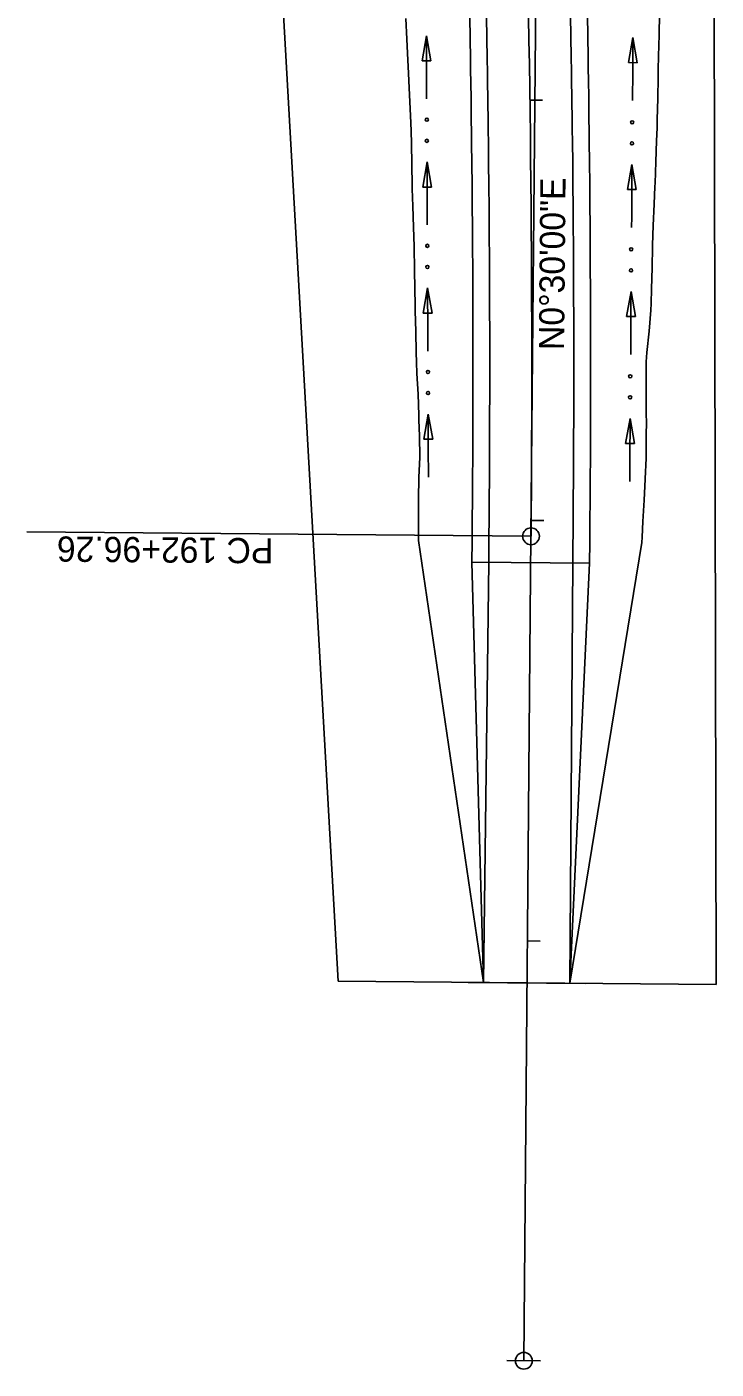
# Model space of a CAD drawing. Extents: x 1 to 1477871, y 1 to 1872901.
# Drawn here: x 1438513.3 to 1438677.3, y 1869035 to 1869354.3 of the extents above; entities that cross this region are included whole.
import ezdxf

# ---------------------------------------------------------------- set-up
doc = ezdxf.new("R2010")
doc.units = 0
for name, color, linetype in [('R_Horz Alg', 7, 'Continuous'), ('R_Horz Alg Annot', 7, 'Continuous'), ('R_No Plot', 7, 'Continuous'), ('R_Proposed Const Limits_Cut', 7, 'Continuous'), ('R_Proposed Road_Lane', 7, 'Continuous'), ('R_Proposed Road_Shoulder', 7, 'Continuous'), ('R_ROW', 7, 'Continuous'), ('R_Water', 7, 'Continuous')]:
    doc.layers.add(name, color=color, linetype=linetype)

msp = doc.modelspace()

# ---------------------------------------------------------------- linework, layer by layer
at = {"layer": 'R_Horz Alg'}
msp.add_line((1438631.55, 1869037.01), (1438633.26, 1869233.13), dxfattribs=at)
msp.add_arc((1434049.78, 1869273.13), 4583.66, 359.5, 3.99213, dxfattribs=at)
at = {"layer": 'R_Horz Alg Annot'}
msp.add_line((1438633.26, 1869233.13), (1438634.83, 1869412.9), dxfattribs=at)
for points in [[(1438635.99, 1869336.91), (1438632.99, 1869336.87)], [(1438633.26, 1869233.13), (1438513.27, 1869234.18)], [(1438636.29, 1869236.85), (1438633.29, 1869236.87)], [(1438635.42, 1869136.85), (1438632.42, 1869136.87)], [(1438627.55, 1869037.05), (1438635.55, 1869036.98)], [(1438627.55, 1869037.05), (1438635.55, 1869036.98)]]:
    msp.add_lwpolyline(points, dxfattribs=at)
for centre in [(1438633.26, 1869233.13), (1438631.55, 1869037.01)]:
    msp.add_circle(centre, 2, dxfattribs=at)
at = {"layer": 'R_No Plot'}
for p, q in [((1438619.21, 1869226.99), (1438647.21, 1869226.75)), ((1438618.34, 1869127), (1438646.33, 1869126.75))]:
    msp.add_line(p, q, dxfattribs=at)
at = {"layer": 'R_Proposed Const Limits_Cut'}
for points in [[(1438621.97, 1869126.96), (1438606.5, 1869232.1), (1438606.49, 1869233.36), (1438606.45, 1869237.08), (1438606.5, 1869242.05), (1438606.58, 1869247.02), (1438606.58, 1869247.1), (1438606.83, 1869251.99), (1438606.71, 1869256.96), (1438606.6, 1869260.85), (1438606.57, 1869261.94), (1438606.37, 1869266.91), (1438606.07, 1869271.88), (1438605.99, 1869274.59), (1438605.94, 1869276.85), (1438605.82, 1869281.82), (1438605.71, 1869286.79), (1438605.68, 1869288.32), (1438605.61, 1869291.76), (1438605.53, 1869296.73), (1438605.46, 1869301.69), (1438605.45, 1869302.06), (1438605.3, 1869306.66), (1438605.12, 1869311.63), (1438604.99, 1869315.8), (1438604.98, 1869316.6), (1438604.9, 1869321.57), (1438604.79, 1869326.54), (1438604.71, 1869329.53), (1438604.66, 1869331.5), (1438604.46, 1869336.47), (1438604.2, 1869341.44), (1438604.1, 1869343.26), (1438603.94, 1869346.4), (1438603.7, 1869351.37), (1438603.47, 1869356.33)], [(1438642.52, 1869126.79), (1438659.62, 1869231.64), (1438659.69, 1869232.9), (1438659.89, 1869236.66), (1438660.19, 1869241.69), (1438660.44, 1869246.71), (1438660.44, 1869246.8), (1438660.64, 1869251.74), (1438660.7, 1869256.77), (1438660.72, 1869260.7), (1438660.71, 1869261.8), (1438660.67, 1869266.83), (1438660.66, 1869271.86), (1438660.66, 1869274.6), (1438660.86, 1869276.89), (1438661.35, 1869281.92), (1438661.79, 1869286.95), (1438661.88, 1869288.51), (1438661.98, 1869291.99), (1438662.1, 1869297.02), (1438662.17, 1869302.05), (1438662.17, 1869302.42), (1438662.32, 1869307.08), (1438662.57, 1869312.12), (1438662.77, 1869316.34), (1438662.78, 1869317.15), (1438662.95, 1869322.19), (1438663.14, 1869327.22), (1438663.26, 1869330.26), (1438663.33, 1869332.26), (1438663.43, 1869337.29), (1438663.5, 1869342.32), (1438663.53, 1869344.17), (1438663.62, 1869347.36), (1438663.74, 1869352.4), (1438663.85, 1869357.43)]]:
    msp.add_lwpolyline(points, dxfattribs=at)
at = {"layer": 'R_Proposed Road_Lane'}
for p, q in [((1438623.21, 1869226.96), (1438621.97, 1869126.96)), ((1438643.21, 1869226.78), (1438642.52, 1869126.79))]:
    msp.add_line(p, q, dxfattribs=at)
for points in [[(1438623.21, 1869226.96), (1438623.25, 1869231.96), (1438623.26, 1869233.22), (1438623.29, 1869236.95), (1438623.33, 1869241.94), (1438623.36, 1869246.93), (1438623.36, 1869247.01), (1438623.39, 1869251.92), (1438623.41, 1869256.91), (1438623.42, 1869260.8), (1438623.42, 1869261.89), (1438623.43, 1869266.88), (1438623.44, 1869271.87), (1438623.44, 1869274.59), (1438623.44, 1869276.86), (1438623.43, 1869281.85), (1438623.42, 1869286.84), (1438623.41, 1869288.38), (1438623.4, 1869291.83), (1438623.38, 1869296.82), (1438623.35, 1869301.81), (1438623.34, 1869302.18), (1438623.31, 1869306.79), (1438623.27, 1869311.78), (1438623.24, 1869315.97), (1438623.23, 1869316.77), (1438623.18, 1869321.76), (1438623.12, 1869326.75), (1438623.09, 1869329.76), (1438623.06, 1869331.74), (1438623, 1869336.73), (1438622.92, 1869341.72), (1438622.9, 1869343.55), (1438622.84, 1869346.71), (1438622.76, 1869351.69), (1438622.67, 1869356.68)], [(1438643.21, 1869226.78), (1438643.25, 1869231.78), (1438643.26, 1869233.04), (1438643.29, 1869236.79), (1438643.33, 1869241.8), (1438643.36, 1869246.81), (1438643.36, 1869246.89), (1438643.39, 1869251.82), (1438643.41, 1869256.83), (1438643.42, 1869260.75), (1438643.42, 1869261.84), (1438643.43, 1869266.86), (1438643.44, 1869271.87), (1438643.44, 1869274.6), (1438643.44, 1869276.88), (1438643.43, 1869281.89), (1438643.42, 1869286.9), (1438643.41, 1869288.45), (1438643.4, 1869291.91), (1438643.38, 1869296.92), (1438643.35, 1869301.93), (1438643.34, 1869302.3), (1438643.31, 1869306.94), (1438643.27, 1869311.95), (1438643.24, 1869316.15), (1438643.23, 1869316.96), (1438643.18, 1869321.98), (1438643.12, 1869326.99), (1438643.08, 1869330.01), (1438643.06, 1869332), (1438642.99, 1869337.01), (1438642.92, 1869342.02), (1438642.89, 1869343.86), (1438642.84, 1869347.03), (1438642.76, 1869352.04), (1438642.67, 1869357.05)]]:
    msp.add_lwpolyline(points, dxfattribs=at)
at = {"layer": 'R_Proposed Road_Shoulder'}
for p, q in [((1438619.21, 1869226.99), (1438621.97, 1869126.96)), ((1438642.52, 1869126.79), (1438647.21, 1869226.75))]:
    msp.add_line(p, q, dxfattribs=at)
for points in [[(1438619.21, 1869226.99), (1438619.25, 1869231.99), (1438619.26, 1869233.25), (1438619.29, 1869236.98), (1438619.33, 1869241.97), (1438619.36, 1869246.95), (1438619.36, 1869247.03), (1438619.39, 1869251.93), (1438619.41, 1869256.92), (1438619.42, 1869260.81), (1438619.42, 1869261.9), (1438619.43, 1869266.89), (1438619.44, 1869271.87), (1438619.44, 1869274.59), (1438619.44, 1869276.86), (1438619.43, 1869281.84), (1438619.42, 1869286.83), (1438619.41, 1869288.37), (1438619.4, 1869291.81), (1438619.38, 1869296.8), (1438619.35, 1869301.78), (1438619.34, 1869302.15), (1438619.31, 1869306.77), (1438619.27, 1869311.75), (1438619.24, 1869315.93), (1438619.23, 1869316.74), (1438619.18, 1869321.72), (1438619.12, 1869326.7), (1438619.09, 1869329.71), (1438619.06, 1869331.69), (1438619, 1869336.67), (1438618.92, 1869341.66), (1438618.9, 1869343.49), (1438618.85, 1869346.64), (1438618.76, 1869351.62), (1438618.67, 1869356.61)], [(1438647.21, 1869226.75), (1438647.25, 1869231.75), (1438647.26, 1869233.01), (1438647.29, 1869236.76), (1438647.33, 1869241.77), (1438647.36, 1869246.79), (1438647.36, 1869246.87), (1438647.39, 1869251.8), (1438647.41, 1869256.82), (1438647.42, 1869260.74), (1438647.42, 1869261.83), (1438647.43, 1869266.85), (1438647.44, 1869271.87), (1438647.44, 1869274.6), (1438647.44, 1869276.88), (1438647.43, 1869281.9), (1438647.42, 1869286.91), (1438647.41, 1869288.46), (1438647.4, 1869291.93), (1438647.38, 1869296.94), (1438647.35, 1869301.96), (1438647.34, 1869302.33), (1438647.31, 1869306.97), (1438647.27, 1869311.99), (1438647.24, 1869316.19), (1438647.23, 1869317), (1438647.18, 1869322.02), (1438647.12, 1869327.03), (1438647.08, 1869330.05), (1438647.06, 1869332.05), (1438646.99, 1869337.06), (1438646.92, 1869342.08), (1438646.89, 1869343.92), (1438646.84, 1869347.09), (1438646.76, 1869352.11), (1438646.67, 1869357.12)]]:
    msp.add_lwpolyline(points, dxfattribs=at)
at = {"layer": 'R_ROW'}
for p, q in [((1438587.34, 1869127.27), (1438531.34, 1870121.98)), ((1438676.17, 1869699.24), (1438677.33, 1869126.48)), ((1438677.33, 1869126.48), (1438587.34, 1869127.27))]:
    msp.add_line(p, q, dxfattribs=at)
at = {"layer": 'R_Water'}
for p, q in [((1438608.38, 1869352.2), (1438607.34, 1869346.2)), ((1438609.45, 1869346.21), (1438608.38, 1869352.2)), ((1438657.53, 1869351.8), (1438656.43, 1869345.8)), ((1438658.55, 1869345.79), (1438657.53, 1869351.8)), ((1438607.34, 1869346.2), (1438609.45, 1869346.21)), ((1438656.43, 1869345.8), (1438658.55, 1869345.79)), ((1438608.52, 1869322.2), (1438607.48, 1869316.2)), ((1438609.59, 1869316.21), (1438608.52, 1869322.2)), ((1438657.3, 1869321.59), (1438656.21, 1869315.6)), ((1438658.32, 1869315.59), (1438657.3, 1869321.59)), ((1438607.48, 1869316.2), (1438609.59, 1869316.21)), ((1438656.21, 1869315.6), (1438658.32, 1869315.59)), ((1438608.66, 1869292.2), (1438607.61, 1869286.2)), ((1438609.73, 1869286.21), (1438608.66, 1869292.2)), ((1438657.07, 1869291.39), (1438655.98, 1869285.39)), ((1438658.1, 1869285.38), (1438657.07, 1869291.39)), ((1438607.61, 1869286.2), (1438609.73, 1869286.21)), ((1438655.98, 1869285.39), (1438658.1, 1869285.38)), ((1438608.8, 1869262.2), (1438607.75, 1869256.2)), ((1438609.87, 1869256.21), (1438608.8, 1869262.2)), ((1438656.85, 1869261.18), (1438655.75, 1869255.19)), ((1438657.87, 1869255.18), (1438656.85, 1869261.18)), ((1438607.75, 1869256.2), (1438609.87, 1869256.21)), ((1438655.75, 1869255.19), (1438657.87, 1869255.18))]:
    msp.add_line(p, q, dxfattribs=at)
for points in [[(1438608.42, 1869337.2), (1438608.41, 1869339.72), (1438608.41, 1869341.61), (1438608.4, 1869344.71), (1438608.39, 1869349.69), (1438608.38, 1869352.2)], [(1438657.44, 1869336.8), (1438657.45, 1869339.32), (1438657.46, 1869341.2), (1438657.48, 1869344.3), (1438657.51, 1869349.28), (1438657.53, 1869351.8)], [(1438608.56, 1869307.2), (1438608.55, 1869309.72), (1438608.55, 1869311.61), (1438608.54, 1869314.71), (1438608.53, 1869319.69), (1438608.52, 1869322.2)], [(1438657.21, 1869306.59), (1438657.23, 1869309.11), (1438657.24, 1869310.99), (1438657.25, 1869314.09), (1438657.28, 1869319.08), (1438657.3, 1869321.59)], [(1438608.7, 1869277.2), (1438608.69, 1869279.72), (1438608.69, 1869281.61), (1438608.68, 1869284.71), (1438608.66, 1869289.69), (1438608.66, 1869292.2)], [(1438656.99, 1869276.39), (1438657, 1869278.91), (1438657.01, 1869280.79), (1438657.03, 1869283.89), (1438657.06, 1869288.87), (1438657.08, 1869291.39)], [(1438608.84, 1869247.2), (1438608.83, 1869249.72), (1438608.82, 1869251.61), (1438608.81, 1869254.71), (1438608.8, 1869259.69), (1438608.8, 1869262.2)], [(1438656.76, 1869246.18), (1438656.78, 1869248.7), (1438656.79, 1869250.59), (1438656.8, 1869253.69), (1438656.83, 1869258.67), (1438656.85, 1869261.18)]]:
    msp.add_lwpolyline(points, dxfattribs=at)
for centre in [(1438608.46, 1869332.22), (1438657.33, 1869331.61), (1438608.47, 1869327.21), (1438657.3, 1869326.6), (1438608.6, 1869302.22), (1438657.11, 1869301.4), (1438608.61, 1869297.21), (1438657.07, 1869296.39), (1438608.74, 1869272.22), (1438656.88, 1869271.2), (1438608.75, 1869267.21), (1438656.85, 1869266.19)]:
    msp.add_circle(centre, 0.375, dxfattribs=at)

# ---------------------------------------------------------------- texts
at = {"layer": 'R_Horz Alg Annot'}
for s, rotation, p in [('N0%%d30\'00"E', 89.5, (1438641.14, 1869277.41)), ('PC 192+96.26', 179.5, (1438571.98, 1869232.66))]:
    msp.add_text(s, height=6, rotation=rotation, dxfattribs=at).set_placement(p)

doc.saveas('drawing.dxf')
